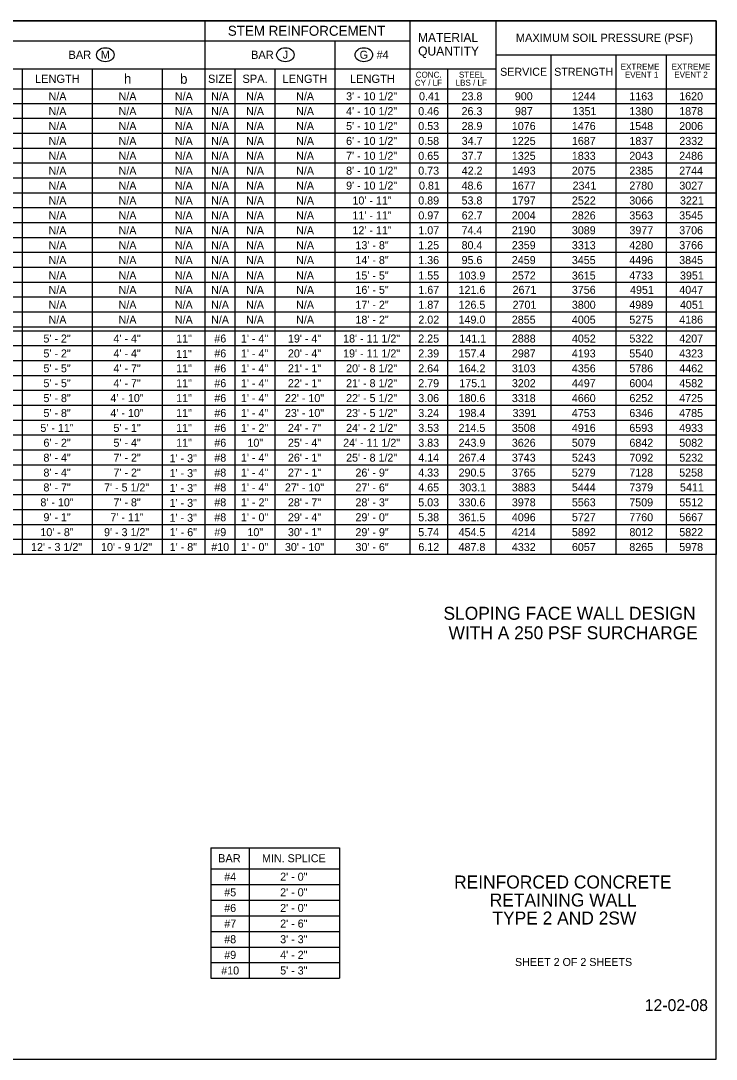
# Model space of a CAD drawing. Extents: x 99862 to 103151, y 100000 to 105076.
# Drawn here: x 101760 to 103151, y 103000 to 105076 of the extents above; entities that cross this region are included whole.
import ezdxf

# ---------------------------------------------------------------- set-up
doc = ezdxf.new("R2010")
doc.units = 0
for name, color, linetype in [('Level 1', 7, 'Continuous'), ('Level 20', 7, 'Continuous'), ('Level 21', 7, 'Continuous'), ('Level 4', 7, 'Continuous'), ('Level 60', 7, 'Continuous'), ('Level 62', 7, 'Continuous'), ('Level 63', 7, 'Continuous')]:
    doc.layers.add(name, color=color, linetype=linetype)

msp = doc.modelspace()

# ---------------------------------------------------------------- linework, layer by layer
at = {"layer": 'Level 1'}
msp.add_lwpolyline([(99862, 102999.5), (103151, 102999.5), (103151, 105075.5), (99862, 105075.5)], close=True, dxfattribs=at)
at = {"layer": 'Level 20'}
for centre in [(101929.5, 105007.5), (102289.5, 105007.5), (102446.4, 105007.5)]:
    msp.add_ellipse(centre, major_axis=(-17.5, 0), ratio=0.8, dxfattribs=at)
at = {"layer": 'Level 4'}
for p, q in [((102129, 104008.6), (102129, 105075.5)), ((102539, 104008.6), (102539, 105075.5)), ((102711, 104008.6), (102711, 105075.5)), ((100399, 105035.5), (102539, 105035.5)), ((102389, 104008.6), (102389, 105035.5)), ((102711, 105007.5), (103151, 105007.5)), ((102821, 104008.6), (102821, 105007.5)), ((102951, 104008.6), (102951, 105007.5)), ((99999, 104979.5), (102711, 104979.5)), ((101764, 104008.6), (101764, 104979.5)), ((101904, 104008.6), (101904, 104979.5)), ((102044, 104008.6), (102044, 104979.5)), ((102189, 104008.6), (102189, 104979.5)), ((102269, 104008.6), (102269, 104979.5)), ((102614, 104008.6), (102614, 104979.5)), ((99924, 104939.5), (103151, 104939.5)), ((103151, 104909.7), (99924, 104909.7)), ((103151, 104880), (99924, 104880)), ((103151, 104850.2), (99924, 104850.2)), ((103151, 104820.4), (99924, 104820.4)), ((103151, 104790.6), (99924, 104790.6)), ((103151, 104760.9), (99924, 104760.9)), ((103151, 104731.1), (99924, 104731.1)), ((103151, 104701.3), (99924, 104701.3)), ((103151, 104671.6), (99924, 104671.6)), ((103151, 104641.8), (99924, 104641.8)), ((103151, 104612), (99924, 104612)), ((103151, 104582.2), (99924, 104582.2)), ((103151, 104552.5), (99924, 104552.5)), ((103151, 104522.7), (99924, 104522.7)), ((103151, 104492.9), (99924, 104492.9)), ((103151, 104463.2), (99924, 104463.2)), ((103151, 104455.2), (99924, 104455.2)), ((103151, 104425.4), (99924, 104425.4)), ((103151, 104395.6), (99924, 104395.6)), ((103151, 104365.8), (99924, 104365.8)), ((103151, 104336.1), (99924, 104336.1)), ((103151, 104306.3), (99924, 104306.3)), ((103151, 104276.5), (99924, 104276.5)), ((103151, 104246.8), (99924, 104246.8)), ((103151, 104217), (99924, 104217)), ((103151, 104187.2), (99924, 104187.2)), ((103151, 104157.4), (99924, 104157.4)), ((103151, 104127.7), (99924, 104127.7)), ((103151, 104097.9), (99924, 104097.9)), ((103151, 104068.1), (99924, 104068.1)), ((103151, 104038.4), (99924, 104038.4)), ((102140.6, 103422.4), (102397.6, 103422.4)), ((102140.6, 103422.4), (102140.6, 103161.3)), ((102217.2, 103422.4), (102217.2, 103161.3)), ((102397.6, 103422.4), (102397.6, 103161.3)), ((102140.6, 103380.1), (102397.6, 103380.1)), ((102140.6, 103348.8), (102397.6, 103348.8)), ((102140.6, 103317.6), (102397.6, 103317.6)), ((102140.6, 103286.3), (102397.6, 103286.3)), ((102140.6, 103255.1), (102397.6, 103255.1)), ((102140.6, 103223.8), (102397.6, 103223.8)), ((102140.6, 103192.6), (102397.6, 103192.6)), ((102140.6, 103161.3), (102397.6, 103161.3))]:
    msp.add_line(p, q, dxfattribs=at)
for points in [[(99924, 105075.5), (103151, 105075.5)], [(103151, 104008.6), (99924, 104008.6), (99924, 105075.5)], [(103151, 105075.5), (103151, 104008.6)], [(103051, 105007.5), (103051, 104012.6)]]:
    msp.add_lwpolyline(points, dxfattribs=at)
at = {"layer": 'Level 60'}
msp.add_line((103151, 105075.5), (103151, 105075.5), dxfattribs=at)

# ---------------------------------------------------------------- texts
at = {"layer": 'Level 1'}
msp.add_text('12-02-08', height=23.62, dxfattribs=at).set_placement((103008, 103095.8))
at = {"layer": 'Level 20'}
for s, height, p in [('STEM REINFORCEMENT', 20, (102174.4, 105045.5)), ('MATERIAL', 18, (102554.5, 105033)), ('MAXIMUM SOIL PRESSURE (PSF)', 16.5, (102750.3, 105033.3)), ('BAR', 16.5, (101855.8, 104999.3)), ('M', 16, (101920.5, 104999.7)), ('BAR', 16.5, (102220.8, 104999.3)), ('J', 16, (102284.2, 104999.8)), ('G', 16, (102438, 104999.6)), ('#4', 16, (102471.9, 104999.5)), ('QUANTITY', 18, (102554.9, 105006)), ('EXTREME ', 12, (102960, 104977.5)), ('EXTREME', 12, (103061.8, 104977.8)), ('LENGTH', 16.5, (101788.7, 104951.3)), ('h', 20, (101966.6, 104949.5)), ('b', 20, (102078.8, 104949.5)), ('SIZE', 16.5, (102134.7, 104951.3)), ('SPA.', 16.5, (102203.6, 104951.3)), ('LENGTH', 16.5, (102283.7, 104951.3)), ('LENGTH', 16.5, (102418.7, 104951.3)), ('CONC.', 12, (102550.2, 104961.6)), ('STEEL', 12, (102636.5, 104961.8)), ('SERVICE', 16, (102718.9, 104965.5)), ('STRENGTH', 16, (102827, 104965.5)), ('EVENT 1', 12, (102968.3, 104961.5)), ('EVENT 2', 12, (103067.1, 104961.8)), ('CY / LF', 12, (102548.3, 104945.6)), ('LBS / LF', 12, (102629.9, 104945.8))]:
    msp.add_text(s, height=height, dxfattribs=at).set_placement(p)
for p in [(101816, 104916.6), (101956, 104916.6), (102068.5, 104916.6), (102141, 104916.6), (102211, 104916.6), (102311, 104916.6), (101816, 104886.8), (101956, 104886.8), (102068.5, 104886.8), (102141, 104886.8), (102211, 104886.8), (102311, 104886.8), (101816, 104857.1), (101956, 104857.1), (102068.5, 104857.1), (102141, 104857.1), (102211, 104857.1), (102311, 104857.1), (101816, 104827.3), (101956, 104827.3), (102068.5, 104827.3), (102141, 104827.3), (102211, 104827.3), (102311, 104827.3), (101816, 104797.5), (101956, 104797.5), (102068.5, 104797.5), (102141, 104797.5), (102211, 104797.5), (102311, 104797.5), (101816, 104767.8), (101956, 104767.8), (102068.5, 104767.8), (102141, 104767.8), (102211, 104767.8), (102311, 104767.8), (101816, 104738), (101956, 104738), (102068.5, 104738), (102141, 104738), (102211, 104738), (102311, 104738), (101816, 104708.2), (101956, 104708.2), (102068.5, 104708.2), (102141, 104708.2), (102211, 104708.2), (102311, 104708.2), (101816, 104678.4), (101956, 104678.4), (102068.5, 104678.4), (102141, 104678.4), (102211, 104678.4), (102311, 104678.4), (101816, 104648.7), (101956, 104648.7), (102068.5, 104648.7), (102141, 104648.7), (102211, 104648.7), (102311, 104648.7), (101816, 104618.9), (101956, 104618.9), (102068.5, 104618.9), (102141, 104618.9), (102211, 104618.9), (102311, 104618.9), (101816, 104589.1), (101956, 104589.1), (102068.5, 104589.1), (102141, 104589.1), (102211, 104589.1), (102311, 104589.1), (101816, 104558.3), (101956, 104558.3), (102068.5, 104558.3), (102141, 104558.3), (102211, 104558.3), (102311, 104558.3), (101816, 104529.6), (101956, 104529.6), (102068.5, 104529.6), (102141, 104529.6), (102211, 104529.6), (102311, 104529.6), (101816, 104499.8), (101956, 104499.8), (102068.5, 104499.8), (102141, 104499.8), (102211, 104499.8), (102311, 104499.8), (101816, 104470), (101956, 104470), (102068.5, 104470), (102141, 104470), (102211, 104470), (102311, 104470), (102311, 104470)]:
    msp.add_text('N/A', height=16, rotation=360, dxfattribs=at).set_placement(p)
at = {"layer": 'Level 21'}
for s, p in [('SLOPING FACE WALL DESIGN ', (102605.5, 103878)), ('WITH A 250 PSF SURCHARGE', (102615.7, 103839))]:
    msp.add_text(s, height=26, rotation=360, dxfattribs=at).set_placement(p)
at = {"layer": 'Level 4'}
for s, height, p in [('3\' - 10 1/2"', 16, (102410.9, 104916.6)), ('0.41', 16, (102556.7, 104916.6)), ('23.8', 16, (102641.8, 104916.6)), ('900', 16, (102748.3, 104916.6)), ('1244', 16, (102862.3, 104916.6)), ('1163', 16, (102977.2, 104916.6)), ('1620', 16, (103077, 104916.6)), ('4\' - 10 1/2"', 16, (102410.9, 104886.8)), ('0.46', 16, (102555.2, 104886.8)), ('26.3', 16, (102641.8, 104886.8)), ('987', 16, (102748.5, 104886.8)), ('1351', 16, (102863.8, 104886.8)), ('1380', 16, (102977.2, 104886.8)), ('1878', 16, (103077, 104886.8)), ('5\' - 10 1/2"', 16, (102410.9, 104857.1)), ('0.53', 16, (102555.2, 104857.1)), ('28.9', 16, (102641.8, 104857.1)), ('1076', 16, (102742.3, 104857.1)), ('1476', 16, (102862.3, 104857.1)), ('1548', 16, (102977.2, 104857.1)), ('2006', 16, (103077, 104857.1)), ('6\' - 10 1/2"', 16, (102410.9, 104827.3)), ('0.58', 16, (102555.2, 104827.3)), ('34.7', 16, (102642, 104827.3)), ('1225', 16, (102742.3, 104827.3)), ('1687', 16, (102862.4, 104827.3)), ('1837', 16, (102977.4, 104827.3)), ('2332', 16, (103077.2, 104827.3)), ('7\' - 10 1/2"', 16, (102410.9, 104797.5)), ('0.65', 16, (102555.2, 104797.5)), ('37.7', 16, (102642, 104797.5)), ('1325', 16, (102742.3, 104797.5)), ('1833', 16, (102862.3, 104797.5)), ('2043', 16, (102977.2, 104797.5)), ('2486', 16, (103077, 104797.5)), ('8\' - 10 1/2"', 16, (102410.9, 104767.8)), ('0.73', 16, (102555.2, 104767.8)), ('42.2', 16, (102642, 104767.8)), ('1493', 16, (102742.3, 104767.8)), ('2075', 16, (102862.3, 104767.8)), ('2385', 16, (102977.2, 104767.8)), ('2744', 16, (103077, 104767.8)), ('9\' - 10 1/2"', 16, (102410.9, 104738)), ('0.81', 16, (102556.7, 104738)), ('48.6', 16, (102641.8, 104738)), ('1677', 16, (102742.4, 104738)), ('2341', 16, (102863.8, 104738)), ('2780', 16, (102977.2, 104738)), ('3027', 16, (103077.2, 104738)), ('10\' - 11"', 16, (102423.6, 104708.2)), ('0.89', 16, (102555.2, 104708.2)), ('53.8', 16, (102641.8, 104708.2)), ('1797', 16, (102742.4, 104708.2)), ('2522', 16, (102862.4, 104708.2)), ('3066', 16, (102977.2, 104708.2)), ('3221', 16, (103078.5, 104708.2)), ('11\' - 11"', 16, (102423.6, 104678.4)), ('0.97', 16, (102555.4, 104678.4)), ('62.7', 16, (102642, 104678.4)), ('2004', 16, (102742.3, 104678.4)), ('2826', 16, (102862.3, 104678.4)), ('3563', 16, (102977.2, 104678.4)), ('3545', 16, (103077, 104678.4)), ('12\' - 11"', 16, (102423.6, 104648.7)), ('1.07', 16, (102555.4, 104648.7)), ('74.4', 16, (102641.8, 104648.7)), ('2190', 16, (102742.3, 104648.7)), ('3089', 16, (102862.3, 104648.7)), ('3977', 16, (102977.4, 104648.7)), ('3706', 16, (103077, 104648.7)), ('13\' - 8"', 16, (102429.6, 104618.9)), ('1.25', 16, (102555.2, 104618.9)), ('80.4', 16, (102641.8, 104618.9)), ('2359', 16, (102742.3, 104618.9)), ('3313', 16, (102862.3, 104618.9)), ('4280', 16, (102977.2, 104618.9)), ('3766', 16, (103077, 104618.9)), ('14\' - 8"', 16, (102429.6, 104589.1)), ('1.36', 16, (102555.2, 104589.1)), ('95.6', 16, (102641.8, 104589.1)), ('2459', 16, (102742.3, 104589.1)), ('3455', 16, (102862.3, 104589.1)), ('4496', 16, (102977.2, 104589.1)), ('3845', 16, (103077, 104589.1)), ('15\' - 5"', 16, (102429.6, 104558.3)), ('1.55', 16, (102555.2, 104558.3)), ('103.9', 16, (102635.8, 104558.3)), ('2572', 16, (102742.4, 104558.3)), ('3615', 16, (102862.3, 104558.3)), ('4733', 16, (102977.2, 104558.3)), ('3951', 16, (103078.5, 104558.3)), ('16\' - 5"', 16, (102429.6, 104529.6)), ('1.67', 16, (102555.4, 104529.6)), ('121.6', 16, (102635.8, 104529.6)), ('2671', 16, (102743.8, 104529.6)), ('3756', 16, (102862.3, 104529.6)), ('4951', 16, (102978.7, 104529.6)), ('4047', 16, (103077.2, 104529.6)), ('17\' - 2"', 16, (102429.6, 104499.8)), ('1.87', 16, (102555.4, 104499.8)), ('126.5', 16, (102635.8, 104499.8)), ('2701', 16, (102743.8, 104499.8)), ('3800', 16, (102862.3, 104499.8)), ('4989', 16, (102977.2, 104499.8)), ('4051', 16, (103078.5, 104499.8)), ('18\' - 2"', 16, (102429.6, 104470)), ('2.02', 16, (102555.4, 104470)), ('149.0', 16, (102635.8, 104470)), ('2855', 16, (102742.3, 104470)), ('4005', 16, (102862.3, 104470)), ('5275', 16, (102977.2, 104470)), ('4186', 16, (103077, 104470)), ('5\' - 2"', 16, (101805.7, 104432.3)), ('4\' - 4"', 16, (101945.7, 104432.3)), ('11"', 16, (102071.1, 104432.3)), ('19\' - 4"', 16, (102294.6, 104432.3)), ('18\' - 11 1/2"', 16, (102404.9, 104432.3)), ('2.25', 16, (102555.2, 104432.3)), ('141.1', 16, (102637.3, 104432.3)), ('2888', 16, (102742.3, 104432.3)), ('4052', 16, (102862.4, 104432.3)), ('5322', 16, (102977.4, 104432.3)), ('4207', 16, (103077.2, 104432.3)), ('5\' - 2"', 16, (101805.7, 104402.5)), ('4\' - 4"', 16, (101945.7, 104402.5)), ('11"', 16, (102070.9, 104401.4)), ('20\' - 4"', 16, (102294.6, 104402.5)), ('19\' - 11 1/2"', 16, (102404.9, 104402.5)), ('2.39', 16, (102555.2, 104402.5)), ('157.4', 16, (102635.8, 104402.5)), ('2987', 16, (102742.4, 104402.5)), ('4193', 16, (102862.3, 104402.5)), ('5540', 16, (102977.2, 104402.5)), ('4323', 16, (103077, 104402.5)), ('5\' - 5"', 16, (101805.7, 104372.7)), ('4\' - 7"', 16, (101945.7, 104372.7)), ('11"', 16, (102071.1, 104372.7)), ('21\' - 1"', 16, (102294.6, 104372.7)), ('20\' - 8 1/2"', 16, (102410.9, 104372.7)), ('2.64', 16, (102555.2, 104372.7)), ('164.2', 16, (102635.9, 104372.7)), ('3103', 16, (102742.3, 104372.7)), ('4356', 16, (102862.3, 104372.7)), ('5786', 16, (102977.2, 104372.7)), ('4462', 16, (103077.2, 104372.7)), ('5\' - 5"', 16, (101805.7, 104343)), ('4\' - 7"', 16, (101945.7, 104343)), ('11"', 16, (102071.1, 104343)), ('22\' - 1"', 16, (102294.6, 104343)), ('21\' - 8 1/2"', 16, (102410.9, 104343)), ('2.79', 16, (102555.2, 104343)), ('175.1', 16, (102637.3, 104343)), ('3202', 16, (102742.4, 104343)), ('4497', 16, (102862.4, 104343)), ('6004', 16, (102977.2, 104343)), ('4582', 16, (103077.2, 104343)), ('5\' - 8"', 16, (101805.7, 104313.2)), ('4\' - 10"', 16, (101939.6, 104313.2)), ('11"', 16, (102071.1, 104313.2)), ('22\' - 10"', 16, (102288.6, 104313.2)), ('22\' - 5 1/2"', 16, (102410.9, 104313.2)), ('3.06', 16, (102555.2, 104313.2)), ('180.6', 16, (102635.8, 104313.2)), ('3318', 16, (102742.3, 104313.2)), ('4660', 16, (102862.3, 104313.2)), ('6252', 16, (102977.4, 104313.2)), ('4725', 16, (103077, 104313.2)), ('5\' - 8"', 16, (101805.7, 104283.4)), ('4\' - 10"', 16, (101939.6, 104283.4)), ('11"', 16, (102071.1, 104283.4)), ('23\' - 10"', 16, (102288.6, 104283.4)), ('23\' - 5 1/2"', 16, (102410.9, 104283.4)), ('3.24', 16, (102555.2, 104283.4)), ('198.4', 16, (102635.8, 104283.4)), ('3391', 16, (102743.8, 104283.4)), ('4753', 16, (102862.3, 104283.4)), ('6346', 16, (102977.2, 104283.4)), ('4785', 16, (103077, 104283.4)), ('5\' - 11"', 16, (101799.6, 104253.6)), ('5\' - 1"', 16, (101945.7, 104253.6)), ('11"', 16, (102071.1, 104253.6)), ('24\' - 7"', 16, (102294.6, 104253.6)), ('24\' - 2 1/2"', 16, (102410.9, 104253.6)), ('3.53', 16, (102555.2, 104253.6)), ('214.5', 16, (102635.8, 104253.6)), ('3508', 16, (102742.3, 104253.6)), ('4916', 16, (102862.3, 104253.6)), ('6593', 16, (102977.2, 104253.6)), ('4933', 16, (103077, 104253.6)), ('6\' - 2"', 16, (101805.7, 104223.9)), ('5\' - 4"', 16, (101945.7, 104223.9)), ('11"', 16, (102071.1, 104223.9)), ('25\' - 4"', 16, (102294.6, 104223.9)), ('24\' - 11 1/2"', 16, (102404.9, 104223.9)), ('3.83', 16, (102555.2, 104223.9)), ('243.9', 16, (102635.8, 104223.9)), ('3626', 16, (102742.3, 104223.9)), ('5079', 16, (102862.3, 104223.9)), ('6842', 16, (102977.4, 104223.9)), ('5082', 16, (103077.2, 104223.9)), ('8\' - 4"', 16, (101805.7, 104194.1)), ('7\' - 2"', 16, (101945.7, 104194.1)), ('1\' - 3"', 16, (102058, 104193)), ('26\' - 1"', 16, (102294.6, 104194.1)), ('25\' - 8 1/2"', 16, (102410.9, 104194.1)), ('4.14', 16, (102555.2, 104194.1)), ('267.4', 16, (102635.8, 104194.1)), ('3743', 16, (102742.3, 104194.1)), ('5243', 16, (102862.3, 104194.1)), ('7092', 16, (102977.4, 104194.1)), ('5232', 16, (103077.2, 104194.1)), ('8\' - 4"', 16, (101805.7, 104164.3)), ('7\' - 2"', 16, (101945.7, 104164.3)), ('1\' - 3"', 16, (102058, 104163.2)), ('27\' - 1"', 16, (102294.6, 104164.3)), ('26\' - 9"', 16, (102429.6, 104164.3)), ('4.33', 16, (102555.2, 104164.3)), ('290.5', 16, (102635.8, 104164.3)), ('3765', 16, (102742.3, 104164.3)), ('5279', 16, (102862.3, 104164.3)), ('7128', 16, (102977.2, 104164.3)), ('5258', 16, (103077, 104164.3)), ('8\' - 7"', 16, (101805.7, 104134.6)), ('7\' - 5 1/2"', 16, (101926.9, 104134.6)), ('1\' - 3"', 16, (102058, 104133.5)), ('27\' - 10"', 16, (102288.6, 104134.6)), ('27\' - 6"', 16, (102429.6, 104134.6)), ('4.65', 16, (102555.2, 104134.6)), ('303.1', 16, (102637.3, 104134.6)), ('3883', 16, (102742.3, 104134.6)), ('5444', 16, (102862.3, 104134.6)), ('7379', 16, (102977.2, 104134.6)), ('5411', 16, (103078.5, 104134.6)), ('8\' - 10"', 16, (101799.6, 104104.8)), ('7\' - 8"', 16, (101945.7, 104104.8)), ('1\' - 3"', 16, (102058, 104103.7)), ('28\' - 7"', 16, (102294.6, 104104.8)), ('28\' - 3"', 16, (102429.6, 104104.8)), ('5.03', 16, (102555.2, 104104.8)), ('330.6', 16, (102635.8, 104104.8)), ('3978', 16, (102742.3, 104104.8)), ('5563', 16, (102862.3, 104104.8)), ('7509', 16, (102977.2, 104104.8)), ('5512', 16, (103077.2, 104104.8)), ('9\' - 1"', 16, (101805.7, 104075)), ('7\' - 11"', 16, (101939.6, 104075)), ('29\' - 4"', 16, (102294.6, 104075)), ('29\' - 0"', 16, (102429.6, 104075)), ('5.38', 16, (102555.2, 104075)), ('361.5', 16, (102635.8, 104075)), ('4096', 16, (102742.3, 104075)), ('5727', 16, (102862.4, 104075)), ('7760', 16, (102977.2, 104075)), ('5667', 16, (103077.2, 104075)), ('1\' - 3"', 16, (102058, 104073.9)), ('10\' - 8"', 16, (101799.6, 104045.2)), ('9\' - 3 1/2"', 16, (101926.9, 104045.2)), ('1\' - 6"', 16, (102058.2, 104045.2)), ('30\' - 1"', 16, (102294.6, 104045.2)), ('29\' - 9"', 16, (102429.6, 104045.2)), ('5.74', 16, (102555.2, 104045.2)), ('454.5', 16, (102635.8, 104045.2)), ('4214', 16, (102742.3, 104045.2)), ('5892', 16, (102862.4, 104045.2)), ('8012', 16, (102977.4, 104045.2)), ('5822', 16, (103077.2, 104045.2)), ('12\' - 3 1/2"', 16, (101780.9, 104015.5)), ('10\' - 9 1/2"', 16, (101920.9, 104015.5)), ('1\' - 8"', 16, (102058.2, 104015.5)), ('30\' - 10"', 16, (102288.6, 104015.5)), ('30\' - 6"', 16, (102429.6, 104015.5)), ('6.12', 16, (102555.4, 104015.5)), ('487.8', 16, (102635.8, 104015.5)), ('4332', 16, (102742.4, 104015.5)), ('6057', 16, (102862.4, 104015.5)), ('8265', 16, (102977.2, 104015.5)), ('5978', 16, (103077, 104015.5)), ('BAR', 16.5, (102154.8, 103393)), ('MIN. SPLICE', 16, (102242.8, 103393.3)), ('#4', 16, (102167.2, 103356.4)), ('2\' - 0"', 16, (102279.1, 103356.4)), ('#5', 16, (102167.2, 103325.2)), ('2\' - 0"', 16, (102279.1, 103325.2)), ('#6', 16, (102167.2, 103293.9)), ('2\' - 0"', 16, (102279.1, 103293.9)), ('#7', 16, (102167.4, 103262.7)), ('2\' - 6"', 16, (102279.1, 103262.7)), ('#8', 16, (102167.2, 103231.4)), ('3\' - 3"', 16, (102279.1, 103231.4)), ('#9', 16, (102167.2, 103200.2)), ('4\' - 2"', 16, (102279.1, 103200.2)), ('#10', 16, (102161.2, 103168.9)), ('5\' - 3"', 16, (102279.1, 103168.9))]:
    msp.add_text(s, height=height, dxfattribs=at).set_placement(p)
for s, p in [('#6', (102147.4, 104432.3)), ('1\' - 4"', (102200.7, 104432.3)), ('#6', (102147.4, 104402.5)), ('1\' - 4"', (102200.7, 104402.5)), ('#6', (102147.4, 104372.7)), ('1\' - 4"', (102200.7, 104372.7)), ('#6', (102147.4, 104343)), ('1\' - 4"', (102200.7, 104343)), ('#6', (102147.4, 104313.2)), ('1\' - 4"', (102200.7, 104313.2)), ('#6', (102147.4, 104283.4)), ('1\' - 4"', (102200.7, 104283.4)), ('#6', (102147.4, 104253.6)), ('1\' - 2"', (102200.7, 104253.6)), ('#6', (102147.4, 104223.9)), ('10"', (102213.6, 104223.9)), ('#8', (102147.4, 104194.1)), ('1\' - 4"', (102200.7, 104194.1)), ('#8', (102147.4, 104164.3)), ('1\' - 4"', (102200.7, 104164.3)), ('#8', (102147.4, 104134.6)), ('1\' - 4"', (102200.7, 104134.6)), ('#8', (102147.4, 104104.8)), ('1\' - 2"', (102200.7, 104104.8)), ('#8', (102147.4, 104075)), ('1\' - 0"', (102200.7, 104075)), ('#9', (102147.4, 104045.2)), ('10"', (102213.6, 104045.2)), ('#10', (102141.3, 104015.5)), ('1\' - 0"', (102200.7, 104015.5))]:
    msp.add_text(s, height=16, rotation=360, dxfattribs=at).set_placement(p)
at = {"layer": 'Level 62'}
msp.add_text('SHEET 2 OF 2 SHEETS', height=16, dxfattribs=at).set_placement((102748.6, 103185.9))
at = {"layer": 'Level 63'}
for s, p in [('REINFORCED CONCRETE', (102626.8, 103340.8)), ('RETAINING WALL', (102698.1, 103304.8)), ('TYPE 2 AND 2SW', (102703.4, 103268.8))]:
    msp.add_text(s, height=26, dxfattribs=at).set_placement(p)

doc.saveas('drawing.dxf')
